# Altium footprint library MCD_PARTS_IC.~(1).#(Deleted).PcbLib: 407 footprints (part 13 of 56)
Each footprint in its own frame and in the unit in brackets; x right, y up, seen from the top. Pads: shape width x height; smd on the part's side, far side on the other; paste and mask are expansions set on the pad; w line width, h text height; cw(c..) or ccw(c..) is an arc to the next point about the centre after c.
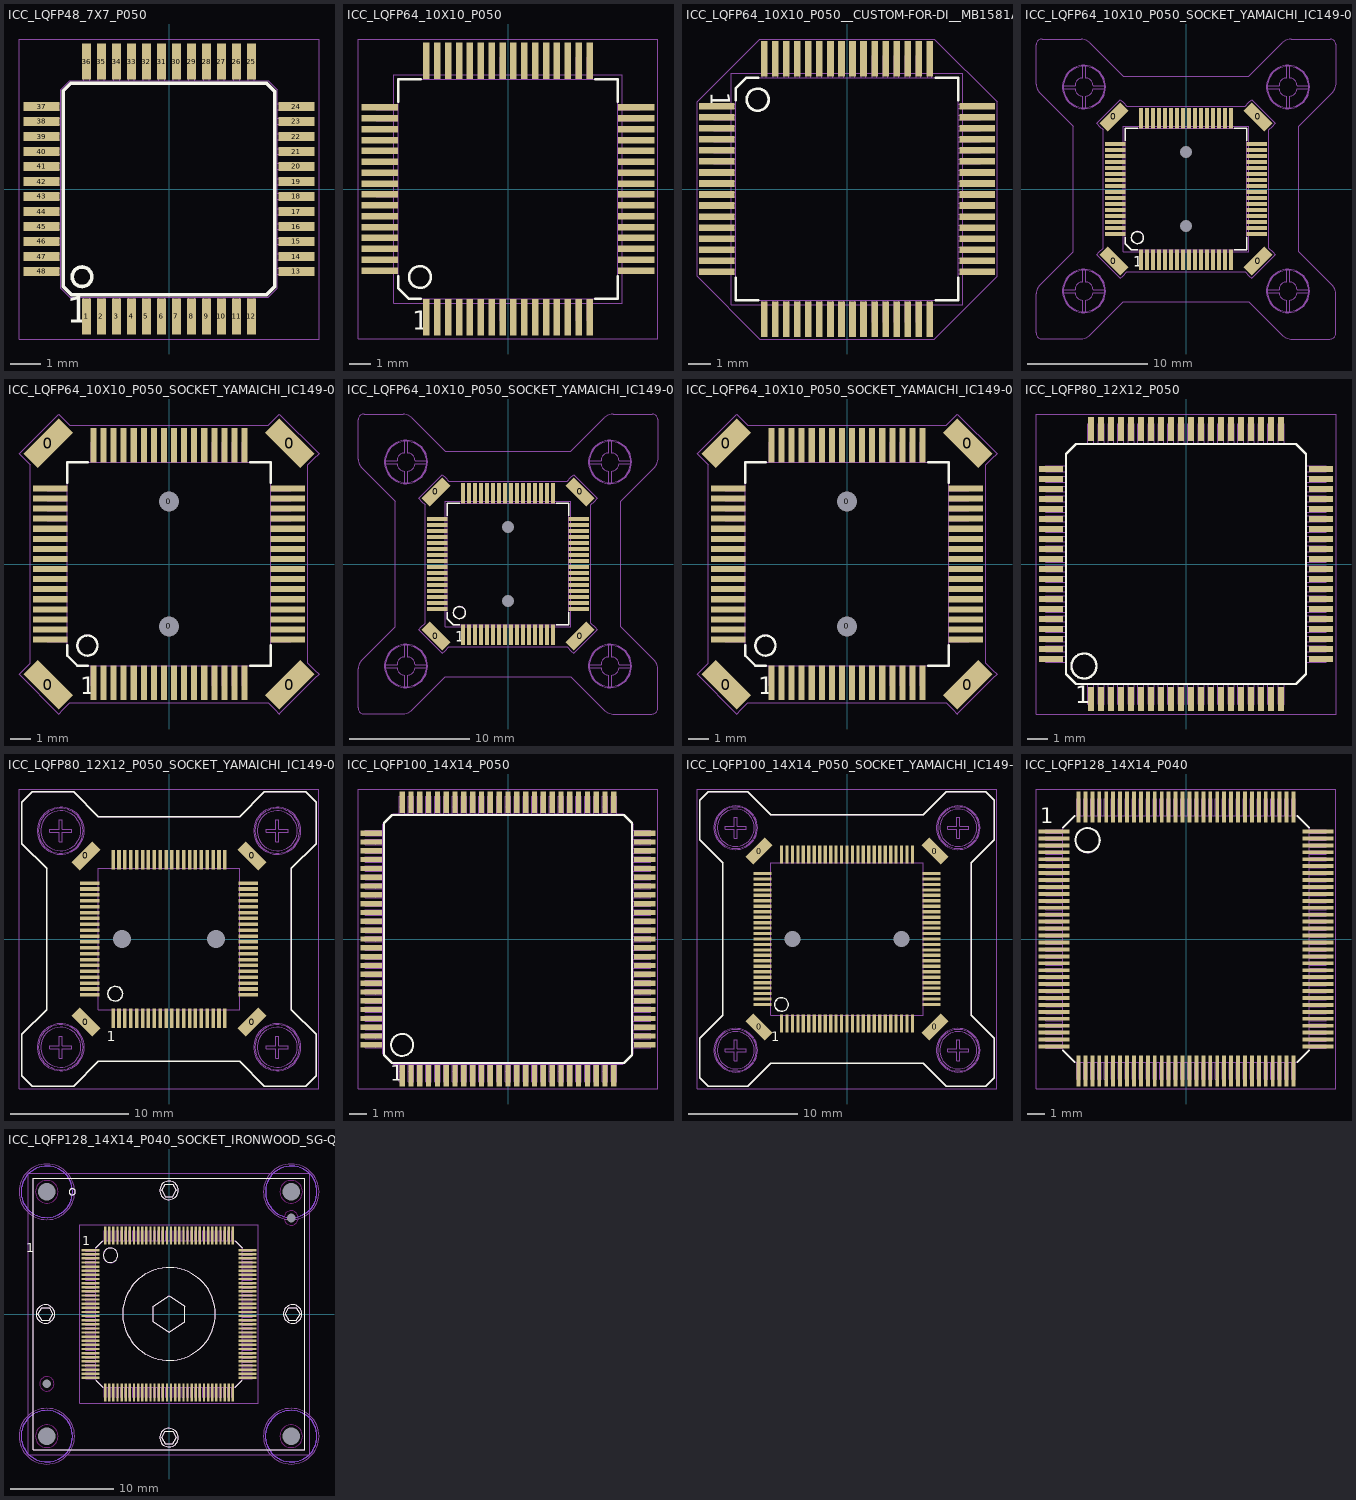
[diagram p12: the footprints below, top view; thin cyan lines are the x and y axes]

## ICC_LQFP48_7X7_P050 [mm]
height 1.6
pads (48):
  rect 0.3x1.2 smd mask+0.05: 1(-2.75,-4.25) 2(-2.25,-4.25) 3(-1.75,-4.25) 4(-1.25,-4.25) 5(-0.75,-4.25) 6(-0.25,-4.25) 7(0.25,-4.25) 8(0.75,-4.25) 9(1.25,-4.25) 10(1.75,-4.25) 11(2.25,-4.25) 12(2.75,-4.25) 25(2.75,4.25) 26(2.25,4.25) 27(1.75,4.25) 28(1.25,4.25) 29(0.75,4.25) 30(0.25,4.25) 31(-0.25,4.25) 32(-0.75,4.25) 33(-1.25,4.25) 34(-1.75,4.25) 35(-2.25,4.25) 36(-2.75,4.25)
  rect 1.2x0.3 smd mask+0.05: 13(4.25,-2.75) 14(4.25,-2.25) 15(4.25,-1.75) 16(4.25,-1.25) 17(4.25,-0.75) 18(4.25,-0.25) 19(4.25,0.25) 20(4.25,0.75) 21(4.25,1.25) 22(4.25,1.75) 23(4.25,2.25) 24(4.25,2.75) 37(-4.25,2.75) 38(-4.25,2.25) 39(-4.25,1.75) 40(-4.25,1.25) 41(-4.25,0.75) 42(-4.25,0.25) 43(-4.25,-0.25) 44(-4.25,-0.75) 45(-4.25,-1.25) 46(-4.25,-1.75) 47(-4.25,-2.25) 48(-4.25,-2.75)
Top Overlay:
  circle w0.12: c-2.9,-2.925 r0.326
  lines w0.12: -3.525,-3.25 -3.525,3 -3.525,3.275 -3.275,3.525 -2.95,3.525 2.85,3.525 3.25,3.525 3.525,3.25 3.525,-2.8 3.525,-3.25 3.25,-3.525 -2.775,-3.525 -3.25,-3.525 -3.525,-3.25
  text "1" at -3.4,-4.75 h1.5
M14-Top Assembly:
  drawing of 209 lines, arcs and shapes, not listed
  text "1" at -3.325,-4.65 h1.5
  text "'.Designator'" at -2,-0.5 h0.75
M16-Top Courtyard:
  lines w0.025: -5,-5 5,-5 5,5 -5,5 -5,-5
3D body "LQFP48_7X7_P050.STEP": height 1.6, standoff 0, extent -4.5,-4.5 4.5,4.5
3D body: height 1.6, standoff 0, extent -3.585,-3.585 3.585,3.585

## ICC_LQFP64_10X10_P050 [mm]
height 1.6
pads (64):
  rect 0.3x1.7 smd mask+0.05: 1(-3.75,-5.9) 2(-3.25,-5.9) 3(-2.75,-5.9) 4(-2.25,-5.9) 5(-1.75,-5.9) 6(-1.25,-5.9) 7(-0.75,-5.9) 8(-0.25,-5.9) 9(0.25,-5.9) 10(0.75,-5.9) 11(1.25,-5.9) 12(1.75,-5.9) 13(2.25,-5.9) 14(2.75,-5.9) 15(3.25,-5.9) 16(3.75,-5.9) 33(3.75,5.9) 34(3.25,5.9) 35(2.75,5.9) 36(2.25,5.9) 37(1.75,5.9) 38(1.25,5.9) 39(0.75,5.9) 40(0.25,5.9) 41(-0.25,5.9) 42(-0.75,5.9) 43(-1.25,5.9) 44(-1.75,5.9) 45(-2.25,5.9) 46(-2.75,5.9) 47(-3.25,5.9) 48(-3.75,5.9)
  rect 1.7x0.3 smd mask+0.05: 17(5.9,-3.75) 18(5.9,-3.25) 19(5.9,-2.75) 20(5.9,-2.25) 21(5.9,-1.75) 22(5.9,-1.25) 23(5.9,-0.75) 24(5.9,-0.25) 25(5.9,0.25) 26(5.9,0.75) 27(5.9,1.25) 28(5.9,1.75) 29(5.9,2.25) 30(5.9,2.75) 31(5.9,3.25) 32(5.9,3.75) 49(-5.9,3.75) 50(-5.9,3.25) 51(-5.9,2.75) 52(-5.9,2.25) 53(-5.9,1.75) 54(-5.9,1.25) 55(-5.9,0.75) 56(-5.9,0.25) 57(-5.9,-0.25) 58(-5.9,-0.75) 59(-5.9,-1.25) 60(-5.9,-1.75) 61(-5.9,-2.25) 62(-5.9,-2.75) 63(-5.9,-3.25) 64(-5.9,-3.75)
Top Overlay:
  circle w0.12: c-4.05,-4.05 r0.5
  lines w0.12: -5.05,-4.025 -5.05,-4.55 -4.55,-5.05 -4.025,-5.05 ; -5.05,4.025 -5.05,5.05 -4.025,5.05 ; 4.025,-5.05 5.05,-5.05 5.05,-4.025 ; 4.025,5.05 5.05,5.05 5.05,4.025
  text "1" at -4.4,-6.775 h1.5
M14-Top Assembly:
  drawing of 202 lines, arcs and shapes, not listed
  text "'.Designator'" at -2,-0.5 h0.75
  text "1" at -3.95,-6.9 h1.2
  text "16" at 3.275,-6.875 h1.2
  text "17" at 6.95,-4.275 h1.2
  text "32" at 6.9,3.2 h1.2
  text "33" at 4.3,6.925 h1.2
  text "48" at -3.15,6.9 h1.2
  text "49" at -6.925,4.325 h1.2
  text "64" at -6.925,-3.175 h1.2
M16-Top Courtyard:
  lines w0.01: -6.9,-6.9 6.9,-6.9 6.9,6.9 -4.925,6.9 -5.675,6.9 -6.9,6.9 -6.9,4.925 -6.9,-6.9
3D body: height 1.6, standoff 0, extent -5.25,-5.25 5.25,5.25
3D body "LQFP64_10X10_P050.STEP": height 1.56, standoff 0, extent -6,-6 6,6

## ICC_LQFP64_10X10_P050__CUSTOM-FOR-DI__MB1581A [mm]
height 13.2
pads (64):
  rect 1.6x0.3 smd mask+0.05: 1(-5.9,3.75) 2(-5.9,3.25) 3(-5.9,2.75) 4(-5.9,2.25) 5(-5.9,1.75) 6(-5.9,1.25) 7(-5.9,0.75) 8(-5.9,0.25) 9(-5.9,-0.25) 10(-5.9,-0.75) 11(-5.9,-1.25) 12(-5.9,-1.75) 13(-5.9,-2.25) 14(-5.9,-2.75) 15(-5.9,-3.25) 16(-5.9,-3.75) 33(5.9,-3.75) 34(5.9,-3.25) 35(5.9,-2.75) 36(5.9,-2.25) 37(5.9,-1.75) 38(5.9,-1.25) 39(5.9,-0.75) 40(5.9,-0.25) 41(5.9,0.25) 42(5.9,0.75) 43(5.9,1.25) 44(5.9,1.75) 45(5.9,2.25) 46(5.9,2.75) 47(5.9,3.25) 48(5.9,3.75)
  rect 0.3x1.6 smd mask+0.05: 17(-3.75,-5.9) 18(-3.25,-5.9) 19(-2.75,-5.9) 20(-2.25,-5.9) 21(-1.75,-5.9) 22(-1.25,-5.9) 23(-0.75,-5.9) 24(-0.25,-5.9) 25(0.25,-5.9) 26(0.75,-5.9) 27(1.25,-5.9) 28(1.75,-5.9) 29(2.25,-5.9) 30(2.75,-5.9) 31(3.25,-5.9) 32(3.75,-5.9) 49(3.75,5.9) 50(3.25,5.9) 51(2.75,5.9) 52(2.25,5.9) 53(1.75,5.9) 54(1.25,5.9) 55(0.75,5.9) 56(0.25,5.9) 57(-0.25,5.9) 58(-0.75,5.9) 59(-1.25,5.9) 60(-1.75,5.9) 61(-2.25,5.9) 62(-2.75,5.9) 63(-3.25,5.9) 64(-3.75,5.9)
Top Overlay:
  circle w0.12: c-4.05,4.05 r0.5
  lines w0.12: -5.05,-4.025 -5.05,-5.05 -4.025,-5.05 ; -5.05,4.025 -5.05,4.55 -4.55,5.05 -4.025,5.05 ; 4.025,-5.05 5.05,-5.05 5.05,-4.025 ; 4.025,5.05 5.05,5.05 5.05,4.025
  text "1" at -6.475,4.4 h1.5
M14-Top Assembly:
  drawing of 202 lines, arcs and shapes, not listed
  text "64" at -3.175,6.925 h1.2
  text "49" at 4.325,6.925 h1.2
  text "48" at 6.9,3.15 h1.2
  text "33" at 6.925,-4.3 h1.2
  text "32" at 3.2,-6.9 h1.2
  text "17" at -4.275,-6.95 h1.2
  text "16" at -6.875,-3.275 h1.2
  text "1" at -6.9,3.95 h1.2
  text "'.Designator'" at -2,-0.5 h0.75
M16-Top Courtyard:
  lines w0.01: -6.8,-3.95 -6.8,3.95 -3.95,6.8 3.95,6.8 6.8,3.95 6.8,-3.95 3.95,-6.8 -3.95,-6.8 -6.8,-3.95
3D body "LQFP64_10X10_P050.STEP": height 1.56, standoff 0, extent -6,-6 6,6

## ICC_LQFP64_10X10_P050_SOCKET_YAMAICHI_IC149-064-069-B5 [mm]
height 12.6
pads (70):
  rect 1x2.5 smd rot 45 mask+0.05: 0(-6,-6) 0(6,6)
  rect 1x2.5 smd rot 135 mask+0.05: 0(-6,6) 0(6,-6)
  round 0.5 hole 1 unplated mask+0.05: 0(0,-3.1) 0(0,3.1)
  rect 0.3x1.7 smd mask+0.05: 1(-3.75,-5.9) 2(-3.25,-5.9) 3(-2.75,-5.9) 4(-2.25,-5.9) 5(-1.75,-5.9) 6(-1.25,-5.9) 7(-0.75,-5.9) 8(-0.25,-5.9) 9(0.25,-5.9) 10(0.75,-5.9) 11(1.25,-5.9) 12(1.75,-5.9) 13(2.25,-5.9) 14(2.75,-5.9) 15(3.25,-5.9) 16(3.75,-5.9) 33(3.75,5.9) 34(3.25,5.9) 35(2.75,5.9) 36(2.25,5.9) 37(1.75,5.9) 38(1.25,5.9) 39(0.75,5.9) 40(0.25,5.9) 41(-0.25,5.9) 42(-0.75,5.9) 43(-1.25,5.9) 44(-1.75,5.9) 45(-2.25,5.9) 46(-2.75,5.9) 47(-3.25,5.9) 48(-3.75,5.9)
  rect 1.7x0.3 smd mask+0.05: 17(5.9,-3.75) 18(5.9,-3.25) 19(5.9,-2.75) 20(5.9,-2.25) 21(5.9,-1.75) 22(5.9,-1.25) 23(5.9,-0.75) 24(5.9,-0.25) 25(5.9,0.25) 26(5.9,0.75) 27(5.9,1.25) 28(5.9,1.75) 29(5.9,2.25) 30(5.9,2.75) 31(5.9,3.25) 32(5.9,3.75) 49(-5.9,3.75) 50(-5.9,3.25) 51(-5.9,2.75) 52(-5.9,2.25) 53(-5.9,1.75) 54(-5.9,1.25) 55(-5.9,0.75) 56(-5.9,0.25) 57(-5.9,-0.25) 58(-5.9,-0.75) 59(-5.9,-1.25) 60(-5.9,-1.75) 61(-5.9,-2.25) 62(-5.9,-2.75) 63(-5.9,-3.25) 64(-5.9,-3.75)
Top Overlay:
  circle w0.12: c-4.05,-4.05 r0.5
  lines w0.12: -5.05,-4.025 -5.05,-4.55 -4.55,-5.05 -4.025,-5.05 ; -5.05,4.025 -5.05,5.05 -4.025,5.05 ; 4.025,-5.05 5.05,-5.05 5.05,-4.025 ; 4.025,5.05 5.05,5.05 5.05,4.025
  text "1" at -4.4,-6.775 h1.5
M14-Top Assembly:
  drawing of 301 lines, arcs and shapes, not listed
  text "64" at -6.925,-3.175 h1.2
  text "49" at -6.925,4.325 h1.2
  text "48" at -3.15,6.9 h1.2
  text "33" at 4.3,6.925 h1.2
  text "32" at 6.9,3.2 h1.2
  text "17" at 6.95,-4.275 h1.2
  text "16" at 3.275,-6.875 h1.2
  text "1" at -3.95,-6.9 h1.2
  text "'.Designator'" at -2,-0.5 h0.75
M16-Top Courtyard:
  lines w0.01: 5.475,-7.45 5.25,-7.225 4.925,-6.9 -4.925,-6.9 -5.25,-7.225 -5.475,-7.45 -7.45,-5.475 -7.225,-5.25 -6.9,-4.925 -6.9,4.925 -7.225,5.25 -7.45,5.475 -5.7,7.225 -5.475,7.45 -5.25,7.225 -4.925,6.9 4.925,6.9 5.25,7.225 5.475,7.45 7.45,5.475 7.225,5.25 6.9,4.925 6.9,-4.925 7.225,-5.25 7.45,-5.475 7.275,-5.65 ; 5.475,-7.45 5.475,-7.45 ; 5.475,-7.45 7.275,-5.65 ; 7.275,-5.65 7.275,-5.65
3D body: height 11, standoff 3.5, extent -9.4,-9.4 -5.25,-5.25
3D body: height 11, standoff 3.5, extent -9.4,-9.4 9.4,9.4
3D body: height 3.5, standoff 0, extent -5.25,-5.25 5.25,5.25
3D body: height 0.2, standoff 0, extent 3.65,-6.675 3.85,-5.25
3D body: height 0.2, standoff 0, extent 3.15,-6.675 3.35,-5.25
3D body: height 0.2, standoff 0, extent 2.65,-6.675 2.85,-5.25
3D body: height 0.2, standoff 0, extent 2.15,-6.675 2.35,-5.25
3D body: height 0.2, standoff 0, extent 1.65,-6.675 1.85,-5.25
3D body: height 0.2, standoff 0, extent 1.15,-6.675 1.35,-5.25
3D body: height 0.2, standoff 0, extent 0.65,-6.675 0.85,-5.25
3D body: height 0.2, standoff 0, extent 0.15,-6.675 0.35,-5.25
3D body: height 0.2, standoff 0, extent -0.35,-6.675 -0.15,-5.25
3D body: height 0.2, standoff 0, extent -0.85,-6.675 -0.65,-5.25
3D body: height 0.2, standoff 0, extent -1.35,-6.675 -1.15,-5.25
3D body: height 0.2, standoff 0, extent -1.85,-6.675 -1.65,-5.25
3D body: height 0.2, standoff 0, extent -2.35,-6.675 -2.15,-5.25
3D body: height 0.2, standoff 0, extent -2.85,-6.675 -2.65,-5.25
3D body: height 0.2, standoff 0, extent -3.35,-6.675 -3.15,-5.25
3D body: height 0.2, standoff 0, extent -3.85,-6.675 -3.65,-5.25
3D body: height 0.2, standoff 0, extent -6.675,-3.85 -5.25,-3.65
3D body: height 0.2, standoff 0, extent -6.675,-3.35 -5.25,-3.15
3D body: height 0.2, standoff 0, extent -6.675,-2.85 -5.25,-2.65
3D body: height 0.2, standoff 0, extent -6.675,-2.35 -5.25,-2.15
3D body: height 0.2, standoff 0, extent -6.675,-1.85 -5.25,-1.65
3D body: height 0.2, standoff 0, extent -6.675,-1.35 -5.25,-1.15
3D body: height 0.2, standoff 0, extent -6.675,-0.85 -5.25,-0.65
3D body: height 0.2, standoff 0, extent -6.675,-0.35 -5.25,-0.15
3D body: height 0.2, standoff 0, extent -6.675,0.15 -5.25,0.35
3D body: height 0.2, standoff 0, extent -6.675,0.65 -5.25,0.85
3D body: height 0.2, standoff 0, extent -6.675,1.15 -5.25,1.35
3D body: height 0.2, standoff 0, extent -6.675,1.65 -5.25,1.85
3D body: height 0.2, standoff 0, extent -6.675,2.15 -5.25,2.35
3D body: height 0.2, standoff 0, extent -6.675,2.65 -5.25,2.85
3D body: height 0.2, standoff 0, extent -6.675,3.15 -5.25,3.35
3D body: height 0.2, standoff 0, extent -6.675,3.65 -5.25,3.85
3D body: height 0.2, standoff 0, extent 5.25,-3.85 6.675,-3.65
3D body: height 0.2, standoff 0, extent 5.25,-3.35 6.675,-3.15
3D body: height 0.2, standoff 0, extent 5.25,-2.85 6.675,-2.65
3D body: height 0.2, standoff 0, extent 5.25,-2.35 6.675,-2.15
3D body: height 0.2, standoff 0, extent 5.25,-1.85 6.675,-1.65
3D body: height 0.2, standoff 0, extent 5.25,-1.35 6.675,-1.15
3D body: height 0.2, standoff 0, extent 5.25,-0.85 6.675,-0.65
3D body: height 0.2, standoff 0, extent 5.25,-0.35 6.675,-0.15
3D body: height 0.2, standoff 0, extent 5.25,0.15 6.675,0.35
3D body: height 0.2, standoff 0, extent 5.25,0.65 6.675,0.85
3D body: height 0.2, standoff 0, extent 5.25,1.15 6.675,1.35
3D body: height 0.2, standoff 0, extent 5.25,1.65 6.675,1.85
3D body: height 0.2, standoff 0, extent 5.25,2.15 6.675,2.35
3D body: height 0.2, standoff 0, extent 5.25,2.65 6.675,2.85
3D body: height 0.2, standoff 0, extent 5.25,3.15 6.675,3.35
3D body: height 0.2, standoff 0, extent 5.25,3.65 6.675,3.85
3D body: height 0.2, standoff 0, extent 3.65,5.25 3.85,6.675
3D body: height 0.2, standoff 0, extent 3.15,5.25 3.35,6.675
3D body: height 0.2, standoff 0, extent 2.65,5.25 2.85,6.675
3D body: height 0.2, standoff 0, extent 2.15,5.25 2.35,6.675
3D body: height 0.2, standoff 0, extent 1.65,5.25 1.85,6.675
3D body: height 0.2, standoff 0, extent 1.15,5.25 1.35,6.675
3D body: height 0.2, standoff 0, extent 0.65,5.25 0.85,6.675
3D body: height 0.2, standoff 0, extent 0.15,5.25 0.35,6.675
3D body: height 0.2, standoff 0, extent -0.35,5.25 -0.15,6.675
3D body: height 0.2, standoff 0, extent -0.85,5.25 -0.65,6.675
3D body: height 0.2, standoff 0, extent -1.35,5.25 -1.15,6.675
3D body: height 0.2, standoff 0, extent -1.85,5.25 -1.65,6.675
3D body: height 0.2, standoff 0, extent -2.35,5.25 -2.15,6.675
3D body: height 0.2, standoff 0, extent -2.85,5.25 -2.65,6.675
3D body: height 0.2, standoff 0, extent -3.35,5.25 -3.15,6.675
3D body: height 11, standoff 3, extent -12.5,5.25 -5.25,12.5
3D body: height 12.6, standoff 11, extent -10.3,6.7 -6.7,10.3
3D body: height 12.6, standoff 11, extent 6.7,6.7 10.3,10.3
3D body: height 11, standoff 3, extent 5.25,5.25 12.5,12.5
3D body: height 12.6, standoff 11, extent 6.7,-10.3 10.3,-6.7
3D body: height 11, standoff 3, extent 5.25,-12.5 12.5,-5.25
3D body: height 12.6, standoff 11, extent -10.3,-10.3 -6.7,-6.7
3D body: height 11, standoff 3, extent -12.5,-12.5 -5.25,-5.25
3D body: height 3.5, standoff 0, extent -7.025,4.975 -4.975,7.025
3D body: height 3.5, standoff 0, extent 4.975,4.975 7.025,7.025
3D body: height 3.5, standoff 0, extent 4.975,-7.025 7.025,-4.975
3D body: height 3.5, standoff 0, extent -7.025,-7.025 -4.975,-4.975
3D body: height 0.2, standoff 0, extent -3.85,5.25 -3.65,6.675
3D body "LQFP64_10X10_P050.STEP": height 5.06, standoff 3.5, extent -6,-6 6,6

## ICC_LQFP64_10X10_P050_SOCKET_YAMAICHI_IC149-064-069-B5_NM [mm]
height 1.6
pads (70):
  rect 1x2.5 smd rot 45 mask+0.05: 0(-6,-6) 0(6,6)
  rect 1x2.5 smd rot 135 mask+0.05: 0(-6,6) 0(6,-6)
  round 0.5 hole 1 unplated mask+0.05: 0(0,-3.1) 0(0,3.1)
  rect 0.3x1.7 smd mask+0.05: 1(-3.75,-5.9) 2(-3.25,-5.9) 3(-2.75,-5.9) 4(-2.25,-5.9) 5(-1.75,-5.9) 6(-1.25,-5.9) 7(-0.75,-5.9) 8(-0.25,-5.9) 9(0.25,-5.9) 10(0.75,-5.9) 11(1.25,-5.9) 12(1.75,-5.9) 13(2.25,-5.9) 14(2.75,-5.9) 15(3.25,-5.9) 16(3.75,-5.9) 33(3.75,5.9) 34(3.25,5.9) 35(2.75,5.9) 36(2.25,5.9) 37(1.75,5.9) 38(1.25,5.9) 39(0.75,5.9) 40(0.25,5.9) 41(-0.25,5.9) 42(-0.75,5.9) 43(-1.25,5.9) 44(-1.75,5.9) 45(-2.25,5.9) 46(-2.75,5.9) 47(-3.25,5.9) 48(-3.75,5.9)
  rect 1.7x0.3 smd mask+0.05: 17(5.9,-3.75) 18(5.9,-3.25) 19(5.9,-2.75) 20(5.9,-2.25) 21(5.9,-1.75) 22(5.9,-1.25) 23(5.9,-0.75) 24(5.9,-0.25) 25(5.9,0.25) 26(5.9,0.75) 27(5.9,1.25) 28(5.9,1.75) 29(5.9,2.25) 30(5.9,2.75) 31(5.9,3.25) 32(5.9,3.75) 49(-5.9,3.75) 50(-5.9,3.25) 51(-5.9,2.75) 52(-5.9,2.25) 53(-5.9,1.75) 54(-5.9,1.25) 55(-5.9,0.75) 56(-5.9,0.25) 57(-5.9,-0.25) 58(-5.9,-0.75) 59(-5.9,-1.25) 60(-5.9,-1.75) 61(-5.9,-2.25) 62(-5.9,-2.75) 63(-5.9,-3.25) 64(-5.9,-3.75)
Top Overlay:
  circle w0.12: c-4.05,-4.05 r0.5
  lines w0.12: -5.05,-4.025 -5.05,-4.55 -4.55,-5.05 -4.025,-5.05 ; -5.05,4.025 -5.05,5.05 -4.025,5.05 ; 4.025,-5.05 5.05,-5.05 5.05,-4.025 ; 4.025,5.05 5.05,5.05 5.05,4.025
  text "1" at -4.4,-6.775 h1.5
M14-Top Assembly:
  drawing of 198 lines, arcs and shapes, not listed
  text "1" at -3.95,-6.9 h1.2
  text "16" at 3.275,-6.875 h1.2
  text "17" at 6.95,-4.275 h1.2
  text "32" at 6.9,3.2 h1.2
  text "33" at 4.3,6.925 h1.2
  text "48" at -3.15,6.9 h1.2
  text "49" at -6.925,4.325 h1.2
  text "64" at -6.925,-3.175 h1.2
  text "'.Designator'" at -2,-0.5 h0.75
M16-Top Courtyard:
  lines w0.01: 5.475,-7.45 7.275,-5.65 ; 5.475,-7.45 5.475,-7.45 ; 5.475,-7.45 5.25,-7.225 4.925,-6.9 -4.925,-6.9 -5.25,-7.225 -5.475,-7.45 -7.45,-5.475 -7.225,-5.25 -6.9,-4.925 -6.9,4.925 -7.225,5.25 -7.45,5.475 -5.7,7.225 -5.475,7.45 -5.25,7.225 -4.925,6.9 4.925,6.9 5.25,7.225 5.475,7.45 7.45,5.475 7.225,5.25 6.9,4.925 6.9,-4.925 7.225,-5.25 7.45,-5.475 7.275,-5.65 ; 7.275,-5.65 7.275,-5.65
3D body "LQFP64_10X10_P050.STEP": height 1.56, standoff 0, extent -6,-6 6,6
3D body: height 1.6, standoff 0, extent -5.05,-5.05 5.05,5.05

## ICC_LQFP64_10X10_P050_SOCKET_YAMAICHI_IC149-064-169-B5 [mm] "MCD-04420"
height 12.6
pads (70):
  rect 1x2.5 smd rot 45 mask+0.05: 0(-6,-6) 0(6,6)
  rect 1x2.5 smd rot 135 mask+0.05: 0(-6,6) 0(6,-6)
  round 0.5 hole 1 unplated mask+0.05: 0(0,-3.1) 0(0,3.1)
  rect 0.3x1.7 smd mask+0.05: 1(-3.75,-5.9) 2(-3.25,-5.9) 3(-2.75,-5.9) 4(-2.25,-5.9) 5(-1.75,-5.9) 6(-1.25,-5.9) 7(-0.75,-5.9) 8(-0.25,-5.9) 9(0.25,-5.9) 10(0.75,-5.9) 11(1.25,-5.9) 12(1.75,-5.9) 13(2.25,-5.9) 14(2.75,-5.9) 15(3.25,-5.9) 16(3.75,-5.9) 33(3.75,5.9) 34(3.25,5.9) 35(2.75,5.9) 36(2.25,5.9) 37(1.75,5.9) 38(1.25,5.9) 39(0.75,5.9) 40(0.25,5.9) 41(-0.25,5.9) 42(-0.75,5.9) 43(-1.25,5.9) 44(-1.75,5.9) 45(-2.25,5.9) 46(-2.75,5.9) 47(-3.25,5.9) 48(-3.75,5.9)
  rect 1.7x0.3 smd mask+0.05: 17(5.9,-3.75) 18(5.9,-3.25) 19(5.9,-2.75) 20(5.9,-2.25) 21(5.9,-1.75) 22(5.9,-1.25) 23(5.9,-0.75) 24(5.9,-0.25) 25(5.9,0.25) 26(5.9,0.75) 27(5.9,1.25) 28(5.9,1.75) 29(5.9,2.25) 30(5.9,2.75) 31(5.9,3.25) 32(5.9,3.75) 49(-5.9,3.75) 50(-5.9,3.25) 51(-5.9,2.75) 52(-5.9,2.25) 53(-5.9,1.75) 54(-5.9,1.25) 55(-5.9,0.75) 56(-5.9,0.25) 57(-5.9,-0.25) 58(-5.9,-0.75) 59(-5.9,-1.25) 60(-5.9,-1.75) 61(-5.9,-2.25) 62(-5.9,-2.75) 63(-5.9,-3.25) 64(-5.9,-3.75)
Top Overlay:
  circle w0.12: c-4.05,-4.05 r0.5
  lines w0.12: -5.05,-4.025 -5.05,-4.55 -4.55,-5.05 -4.025,-5.05 ; -5.05,4.025 -5.05,5.05 -4.025,5.05 ; 4.025,-5.05 5.05,-5.05 5.05,-4.025 ; 4.025,5.05 5.05,5.05 5.05,4.025
  text "1" at -4.4,-6.775 h1.5
M14-Top Assembly:
  drawing of 301 lines, arcs and shapes, not listed
  text "'.Designator'" at 0,0 h0.75
  text "1" at -3.95,-6.9 h1.2
  text "16" at 3.275,-6.875 h1.2
  text "17" at 6.95,-4.275 h1.2
  text "32" at 6.9,3.2 h1.2
  text "33" at 4.3,6.925 h1.2
  text "48" at -3.15,6.9 h1.2
  text "49" at -6.925,4.325 h1.2
  text "64" at -6.925,-3.175 h1.2
M16-Top Courtyard:
  lines w0.01: 5.475,-7.45 7.275,-5.65 ; 5.475,-7.45 5.475,-7.45 ; 5.475,-7.45 5.25,-7.225 4.925,-6.9 -4.925,-6.9 -5.25,-7.225 -5.475,-7.45 -7.45,-5.475 -7.225,-5.25 -6.9,-4.925 -6.9,4.925 -7.225,5.25 -7.45,5.475 -5.7,7.225 -5.475,7.45 -5.25,7.225 -4.925,6.9 4.925,6.9 5.25,7.225 5.475,7.45 7.45,5.475 7.225,5.25 6.9,4.925 6.9,-4.925 7.225,-5.25 7.45,-5.475 7.275,-5.65 ; 7.275,-5.65 7.275,-5.65
3D body "LQFP64_10X10_P050.STEP": height 5.06, standoff 3.5, extent -6,-6 6,6
3D body: height 0.2, standoff 0, extent -3.85,5.25 -3.65,6.675
3D body: height 3.5, standoff 0, extent -7.025,-7.025 -4.975,-4.975
3D body: height 3.5, standoff 0, extent 4.975,-7.025 7.025,-4.975
3D body: height 3.5, standoff 0, extent 4.975,4.975 7.025,7.025
3D body: height 3.5, standoff 0, extent -7.025,4.975 -4.975,7.025
3D body: height 11, standoff 3, extent -12.5,-12.5 -5.25,-5.25
3D body: height 12.6, standoff 11, extent -10.3,-10.3 -6.7,-6.7
3D body: height 11, standoff 3, extent 5.25,-12.5 12.5,-5.25
3D body: height 12.6, standoff 11, extent 6.7,-10.3 10.3,-6.7
3D body: height 11, standoff 3, extent 5.25,5.25 12.5,12.5
3D body: height 12.6, standoff 11, extent 6.7,6.7 10.3,10.3
3D body: height 12.6, standoff 11, extent -10.3,6.7 -6.7,10.3
3D body: height 11, standoff 3, extent -12.5,5.25 -5.25,12.5
3D body: height 0.2, standoff 0, extent -3.35,5.25 -3.15,6.675
3D body: height 0.2, standoff 0, extent -2.85,5.25 -2.65,6.675
3D body: height 0.2, standoff 0, extent -2.35,5.25 -2.15,6.675
3D body: height 0.2, standoff 0, extent -1.85,5.25 -1.65,6.675
3D body: height 0.2, standoff 0, extent -1.35,5.25 -1.15,6.675
3D body: height 0.2, standoff 0, extent -0.85,5.25 -0.65,6.675
3D body: height 0.2, standoff 0, extent -0.35,5.25 -0.15,6.675
3D body: height 0.2, standoff 0, extent 0.15,5.25 0.35,6.675
3D body: height 0.2, standoff 0, extent 0.65,5.25 0.85,6.675
3D body: height 0.2, standoff 0, extent 1.15,5.25 1.35,6.675
3D body: height 0.2, standoff 0, extent 1.65,5.25 1.85,6.675
3D body: height 0.2, standoff 0, extent 2.15,5.25 2.35,6.675
3D body: height 0.2, standoff 0, extent 2.65,5.25 2.85,6.675
3D body: height 0.2, standoff 0, extent 3.15,5.25 3.35,6.675
3D body: height 0.2, standoff 0, extent 3.65,5.25 3.85,6.675
3D body: height 0.2, standoff 0, extent 5.25,3.65 6.675,3.85
3D body: height 0.2, standoff 0, extent 5.25,3.15 6.675,3.35
3D body: height 0.2, standoff 0, extent 5.25,2.65 6.675,2.85
3D body: height 0.2, standoff 0, extent 5.25,2.15 6.675,2.35
3D body: height 0.2, standoff 0, extent 5.25,1.65 6.675,1.85
3D body: height 0.2, standoff 0, extent 5.25,1.15 6.675,1.35
3D body: height 0.2, standoff 0, extent 5.25,0.65 6.675,0.85
3D body: height 0.2, standoff 0, extent 5.25,0.15 6.675,0.35
3D body: height 0.2, standoff 0, extent 5.25,-0.35 6.675,-0.15
3D body: height 0.2, standoff 0, extent 5.25,-0.85 6.675,-0.65
3D body: height 0.2, standoff 0, extent 5.25,-1.35 6.675,-1.15
3D body: height 0.2, standoff 0, extent 5.25,-1.85 6.675,-1.65
3D body: height 0.2, standoff 0, extent 5.25,-2.35 6.675,-2.15
3D body: height 0.2, standoff 0, extent 5.25,-2.85 6.675,-2.65
3D body: height 0.2, standoff 0, extent 5.25,-3.35 6.675,-3.15
3D body: height 0.2, standoff 0, extent 5.25,-3.85 6.675,-3.65
3D body: height 0.2, standoff 0, extent -6.675,3.65 -5.25,3.85
3D body: height 0.2, standoff 0, extent -6.675,3.15 -5.25,3.35
3D body: height 0.2, standoff 0, extent -6.675,2.65 -5.25,2.85
3D body: height 0.2, standoff 0, extent -6.675,2.15 -5.25,2.35
3D body: height 0.2, standoff 0, extent -6.675,1.65 -5.25,1.85
3D body: height 0.2, standoff 0, extent -6.675,1.15 -5.25,1.35
3D body: height 0.2, standoff 0, extent -6.675,0.65 -5.25,0.85
3D body: height 0.2, standoff 0, extent -6.675,0.15 -5.25,0.35
3D body: height 0.2, standoff 0, extent -6.675,-0.35 -5.25,-0.15
3D body: height 0.2, standoff 0, extent -6.675,-0.85 -5.25,-0.65
3D body: height 0.2, standoff 0, extent -6.675,-1.35 -5.25,-1.15
3D body: height 0.2, standoff 0, extent -6.675,-1.85 -5.25,-1.65
3D body: height 0.2, standoff 0, extent -6.675,-2.35 -5.25,-2.15
3D body: height 0.2, standoff 0, extent -6.675,-2.85 -5.25,-2.65
3D body: height 0.2, standoff 0, extent -6.675,-3.35 -5.25,-3.15
3D body: height 0.2, standoff 0, extent -6.675,-3.85 -5.25,-3.65
3D body: height 0.2, standoff 0, extent -3.85,-6.675 -3.65,-5.25
3D body: height 0.2, standoff 0, extent -3.35,-6.675 -3.15,-5.25
3D body: height 0.2, standoff 0, extent -2.85,-6.675 -2.65,-5.25
3D body: height 0.2, standoff 0, extent -2.35,-6.675 -2.15,-5.25
3D body: height 0.2, standoff 0, extent -1.85,-6.675 -1.65,-5.25
3D body: height 0.2, standoff 0, extent -1.35,-6.675 -1.15,-5.25
3D body: height 0.2, standoff 0, extent -0.85,-6.675 -0.65,-5.25
3D body: height 0.2, standoff 0, extent -0.35,-6.675 -0.15,-5.25
3D body: height 0.2, standoff 0, extent 0.15,-6.675 0.35,-5.25
3D body: height 0.2, standoff 0, extent 0.65,-6.675 0.85,-5.25
3D body: height 0.2, standoff 0, extent 1.15,-6.675 1.35,-5.25
3D body: height 0.2, standoff 0, extent 1.65,-6.675 1.85,-5.25
3D body: height 0.2, standoff 0, extent 2.15,-6.675 2.35,-5.25
3D body: height 0.2, standoff 0, extent 2.65,-6.675 2.85,-5.25
3D body: height 0.2, standoff 0, extent 3.15,-6.675 3.35,-5.25
3D body: height 0.2, standoff 0, extent 3.65,-6.675 3.85,-5.25
3D body: height 3.5, standoff 0, extent -5.25,-5.25 5.25,5.25
3D body: height 11, standoff 3.5, extent -9.4,-9.4 9.4,9.4
3D body: height 11, standoff 3.5, extent -9.4,-9.4 -5.25,-5.25

## ICC_LQFP64_10X10_P050_SOCKET_YAMAICHI_IC149-064-169-B5_NM [mm] "MCD-04420"
height 1.6
pads (70):
  rect 1x2.5 smd rot 45 mask+0.05: 0(-6,-6) 0(6,6)
  rect 1x2.5 smd rot 135 mask+0.05: 0(-6,6) 0(6,-6)
  round 0.5 hole 1 unplated mask+0.05: 0(0,-3.1) 0(0,3.1)
  rect 0.3x1.7 smd mask+0.05: 1(-3.75,-5.9) 2(-3.25,-5.9) 3(-2.75,-5.9) 4(-2.25,-5.9) 5(-1.75,-5.9) 6(-1.25,-5.9) 7(-0.75,-5.9) 8(-0.25,-5.9) 9(0.25,-5.9) 10(0.75,-5.9) 11(1.25,-5.9) 12(1.75,-5.9) 13(2.25,-5.9) 14(2.75,-5.9) 15(3.25,-5.9) 16(3.75,-5.9) 33(3.75,5.9) 34(3.25,5.9) 35(2.75,5.9) 36(2.25,5.9) 37(1.75,5.9) 38(1.25,5.9) 39(0.75,5.9) 40(0.25,5.9) 41(-0.25,5.9) 42(-0.75,5.9) 43(-1.25,5.9) 44(-1.75,5.9) 45(-2.25,5.9) 46(-2.75,5.9) 47(-3.25,5.9) 48(-3.75,5.9)
  rect 1.7x0.3 smd mask+0.05: 17(5.9,-3.75) 18(5.9,-3.25) 19(5.9,-2.75) 20(5.9,-2.25) 21(5.9,-1.75) 22(5.9,-1.25) 23(5.9,-0.75) 24(5.9,-0.25) 25(5.9,0.25) 26(5.9,0.75) 27(5.9,1.25) 28(5.9,1.75) 29(5.9,2.25) 30(5.9,2.75) 31(5.9,3.25) 32(5.9,3.75) 49(-5.9,3.75) 50(-5.9,3.25) 51(-5.9,2.75) 52(-5.9,2.25) 53(-5.9,1.75) 54(-5.9,1.25) 55(-5.9,0.75) 56(-5.9,0.25) 57(-5.9,-0.25) 58(-5.9,-0.75) 59(-5.9,-1.25) 60(-5.9,-1.75) 61(-5.9,-2.25) 62(-5.9,-2.75) 63(-5.9,-3.25) 64(-5.9,-3.75)
Top Overlay:
  circle w0.12: c-4.05,-4.05 r0.5
  lines w0.12: -5.05,-4.025 -5.05,-4.55 -4.55,-5.05 -4.025,-5.05 ; -5.05,4.025 -5.05,5.05 -4.025,5.05 ; 4.025,-5.05 5.05,-5.05 5.05,-4.025 ; 4.025,5.05 5.05,5.05 5.05,4.025
  text "1" at -4.4,-6.775 h1.5
M14-Top Assembly:
  drawing of 198 lines, arcs and shapes, not listed
  text "'.Designator'" at 0,0 h0.75
  text "64" at -6.925,-3.175 h1.2
  text "49" at -6.925,4.325 h1.2
  text "48" at -3.15,6.9 h1.2
  text "33" at 4.3,6.925 h1.2
  text "32" at 6.9,3.2 h1.2
  text "17" at 6.95,-4.275 h1.2
  text "16" at 3.275,-6.875 h1.2
  text "1" at -3.95,-6.9 h1.2
M16-Top Courtyard:
  lines w0.01: 5.475,-7.45 5.25,-7.225 4.925,-6.9 -4.925,-6.9 -5.25,-7.225 -5.475,-7.45 -7.45,-5.475 -7.225,-5.25 -6.9,-4.925 -6.9,4.925 -7.225,5.25 -7.45,5.475 -5.7,7.225 -5.475,7.45 -5.25,7.225 -4.925,6.9 4.925,6.9 5.25,7.225 5.475,7.45 7.45,5.475 7.225,5.25 6.9,4.925 6.9,-4.925 7.225,-5.25 7.45,-5.475 7.275,-5.65 ; 5.475,-7.45 5.475,-7.45 ; 5.475,-7.45 7.275,-5.65 ; 7.275,-5.65 7.275,-5.65
3D body: height 1.6, standoff 0, extent -5.05,-5.05 5.05,5.05
3D body "LQFP64_10X10_P050.STEP": height 1.56, standoff 0, extent -6,-6 6,6

## ICC_LQFP80_12X12_P050 [mm] "MCD-02690"
height 1.6
pads (80):
  rect 0.3x1.2 smd mask+0.05: 1(-4.75,-6.75) 2(-4.25,-6.75) 3(-3.75,-6.75) 4(-3.25,-6.75) 5(-2.75,-6.75) 6(-2.25,-6.75) 7(-1.75,-6.75) 8(-1.25,-6.75) 9(-0.75,-6.75) 10(-0.25,-6.75) 11(0.25,-6.75) 12(0.75,-6.75) 13(1.25,-6.75) 14(1.75,-6.75) 15(2.25,-6.75) 16(2.75,-6.75) 17(3.25,-6.75) 18(3.75,-6.75) 19(4.25,-6.75) 20(4.75,-6.75) 41(4.75,6.75) 42(4.25,6.75) 43(3.75,6.75) 44(3.25,6.75) 45(2.75,6.75) 46(2.25,6.75) 47(1.75,6.75) 48(1.25,6.75) 49(0.75,6.75) 50(0.25,6.75) 51(-0.25,6.75) 52(-0.75,6.75) 53(-1.25,6.75) 54(-1.75,6.75) 55(-2.25,6.75) 56(-2.75,6.75) 57(-3.25,6.75) 58(-3.75,6.75) 59(-4.25,6.75) 60(-4.75,6.75)
  rect 1.2x0.3 smd mask+0.05: 21(6.75,-4.75) 22(6.75,-4.25) 23(6.75,-3.75) 24(6.75,-3.25) 25(6.75,-2.75) 26(6.75,-2.25) 27(6.75,-1.75) 28(6.75,-1.25) 29(6.75,-0.75) 30(6.75,-0.25) 31(6.75,0.25) 32(6.75,0.75) 33(6.75,1.25) 34(6.75,1.75) 35(6.75,2.25) 36(6.75,2.75) 37(6.75,3.25) 38(6.75,3.75) 39(6.75,4.25) 40(6.75,4.75) 61(-6.75,4.75) 62(-6.75,4.25) 63(-6.75,3.75) 64(-6.75,3.25) 65(-6.75,2.75) 66(-6.75,2.25) 67(-6.75,1.75) 68(-6.75,1.25) 69(-6.75,0.75) 70(-6.75,0.25) 71(-6.75,-0.25) 72(-6.75,-0.75) 73(-6.75,-1.25) 74(-6.75,-1.75) 75(-6.75,-2.25) 76(-6.75,-2.75) 77(-6.75,-3.25) 78(-6.75,-3.75) 79(-6.75,-4.25) 80(-6.75,-4.75)
Top Overlay:
  circle w0.12: c-5.1,-5.1 r0.625
  lines w0.12: -6,-5.5 -5.5,-6 5.5,-6 6,-5.5 6,5.5 5.5,6 -5.5,6 -6,5.5 -6,-5.5
  text "1" at -5.55,-7.25 h1.5
Top Assembly:
  drawing of 329 lines, arcs and shapes, not listed
  text "41" at 5.2,6.975 h1
  text "60" at -4.35,7 h1
  text "21" at 6.975,-5.2 h1
  text "40" at 7,4.35 h1
  text "'.Designator'" at -2,-0.5 h0.75
  text "80" at -7,-4.35 h1
  text "61" at -6.975,5.2 h1
  text "20" at 4.35,-7 h1
  text "1" at -4.9,-6.975 h1
Top Courtyard:
  lines w0.01: -7.5,-7.5 7.5,-7.5 7.5,7.5 -7.5,7.5 -7.5,-7.5
3D body "User Library-LQFP-80.STEP": height 1.43, standoff -0.01, extent -6.9,-6.9 6.9,6.9

## ICC_LQFP80_12X12_P050_SOCKET_YAMAICHI_IC149-080-130-B5 [mm] "MCD-03131"
height 13.2
pads (86):
  rect 1x2.5 smd rot 45 mask+0.05: 0(-7.071,-7.071) 0(7.071,7.071)
  rect 1x2.5 smd rot 135 mask+0.05: 0(-7.071,7.071) 0(7.071,-7.071)
  round 0 hole 1.5 unplated mask+0.05: 0(-4,0) 0(4,0)
  rect 0.3x1.65 smd mask+0.05: 1(-4.75,-6.725) 2(-4.25,-6.725) 3(-3.75,-6.725) 4(-3.25,-6.725) 5(-2.75,-6.725) 6(-2.25,-6.725) 7(-1.75,-6.725) 8(-1.25,-6.725) 9(-0.75,-6.725) 10(-0.25,-6.725) 11(0.25,-6.725) 12(0.75,-6.725) 13(1.25,-6.725) 14(1.75,-6.725) 15(2.25,-6.725) 16(2.75,-6.725) 17(3.25,-6.725) 18(3.75,-6.725) 19(4.25,-6.725) 20(4.75,-6.725) 41(4.75,6.725) 42(4.25,6.725) 43(3.75,6.725) 44(3.25,6.725) 45(2.75,6.725) 46(2.25,6.725) 47(1.75,6.725) 48(1.25,6.725) 49(0.75,6.725) 50(0.25,6.725) 51(-0.25,6.725) 52(-0.75,6.725) 53(-1.25,6.725) 54(-1.75,6.725) 55(-2.25,6.725) 56(-2.75,6.725) 57(-3.25,6.725) 58(-3.75,6.725) 59(-4.25,6.725) 60(-4.75,6.725)
  rect 1.65x0.3 smd mask+0.05: 21(6.725,-4.75) 22(6.725,-4.25) 23(6.725,-3.75) 24(6.725,-3.25) 25(6.725,-2.75) 26(6.725,-2.25) 27(6.725,-1.75) 28(6.725,-1.25) 29(6.725,-0.75) 30(6.725,-0.25) 31(6.725,0.25) 32(6.725,0.75) 33(6.725,1.25) 34(6.725,1.75) 35(6.725,2.25) 36(6.725,2.75) 37(6.725,3.25) 38(6.725,3.75) 39(6.725,4.25) 40(6.725,4.75) 61(-6.75,4.75) 62(-6.75,4.25) 63(-6.75,3.75) 64(-6.75,3.25) 65(-6.75,2.75) 66(-6.75,2.25) 67(-6.75,1.75) 68(-6.75,1.25) 69(-6.75,0.75) 70(-6.75,0.25) 71(-6.75,-0.25) 72(-6.75,-0.75) 73(-6.75,-1.25) 74(-6.75,-1.75) 75(-6.75,-2.25) 76(-6.75,-2.75) 77(-6.75,-3.25) 78(-6.75,-3.75) 79(-6.75,-4.25) 80(-6.75,-4.75)
Top Overlay:
  circle w0.12: c-4.575,-4.65 r0.625
  lines w0.12: -12.5,-11.625 -11.625,-12.5 -8.1,-12.5 -6,-10.4 6,-10.4 8.1,-12.5 11.625,-12.5 12.5,-11.625 12.5,-8.1 10.4,-6 10.4,6 12.5,8.1 12.5,11.625 11.625,12.5 8.1,12.5 6,10.4 -6,10.4 -8.1,12.5 -11.625,12.5 -12.5,11.625 -12.5,8.1 -10.4,6 -10.4,-6 -12.5,-8.1 -12.5,-11.625
  text "1" at -5.3,-9 h1.5
M14-Top Assembly:
  circle w0.01: c-9.2,9.2 r2
  circle w0.01: c-9.2,9.2 r1.901
  circle w0.01: c-9.2,9.2 r1.7
  circle w0.01: c-9.2,-9.2 r2
  circle w0.01: c-9.2,-9.2 r1.901
  circle w0.01: c-9.2,-9.2 r1.7
  circle w0.01: c9.2,-9.2 r2
  circle w0.01: c9.2,-9.2 r1.901
  circle w0.01: c9.2,-9.2 r1.7
  circle w0.01: c9.2,9.2 r2
  circle w0.01: c9.2,9.2 r1.901
  circle w0.01: c9.2,9.2 r1.7
  lines w0.01: -12.5,-11.625 -11.625,-12.5 -8.1,-12.5 -6,-10.4 6,-10.4 8.1,-12.5 11.625,-12.5 12.5,-11.625 12.5,-8.1 10.4,-6 10.4,6 12.5,8.1 12.5,11.625 11.625,12.5 8.1,12.5 6,10.4 -6,10.4 -8.1,12.5 -11.625,12.5 -12.5,11.625 -12.5,8.1 -10.4,6 -10.4,-6 -12.5,-8.1 -12.5,-11.625 ; -10.15,-9.325 -10.15,-9.2 -10.15,-9.075 -9.325,-9.075 -9.325,-8.25 -9.2,-8.25 -9.075,-8.25 -9.075,-9.075 -8.25,-9.075 -8.25,-9.2 -8.25,-9.325 -9.075,-9.325 -9.075,-10.15 -9.2,-10.15 -9.325,-10.15 -9.325,-9.325 -10.15,-9.325 ; -10.15,9.075 -9.325,9.075 -9.325,8.25 -9.2,8.25 -9.075,8.25 -9.075,9.075 -8.25,9.075 -8.25,9.2 -8.25,9.325 -9.075,9.325 -9.075,10.15 -9.2,10.15 -9.325,10.15 -9.325,9.325 -10.15,9.325 -10.15,9.2 -10.15,9.075 ; -6,-6 6,-6 6,6 -6,6 -6,-6 ; 8.25,-9.325 9.075,-9.325 9.075,-10.15 9.2,-10.15 9.325,-10.15 9.325,-9.325 10.15,-9.325 10.15,-9.2 10.15,-9.075 9.325,-9.075 9.325,-8.25 9.2,-8.25 9.075,-8.25 9.075,-9.075 8.25,-9.075 8.25,-9.2 8.25,-9.325 ; 8.25,9.075 9.075,9.075 9.075,8.25 9.2,8.25 9.325,8.25 9.325,9.075 10.15,9.075 10.15,9.2 10.15,9.325 9.325,9.325 9.325,10.15 9.2,10.15 9.075,10.15 9.075,9.325 8.25,9.325 8.25,9.2 8.25,9.075
  text "20" at 4.6,-6.725 h1
  text "'.Designator'" at -2,-0.5 h0.75
  text "1" at -4.9,-6.725 h1
  text "21" at 6.933,-4.9 h1
  text "40" at 6.725,4.6 h1
  text "41" at 5.15,6.975 h1
  text "60" at -4.525,6.975 h1
  text "61" at -7.1,5.425 h1
  text "80" at -6.75,-4.6 h1
M16-Top Courtyard:
  lines w0.01: -12.75,-12.75 -12.75,12.75 12.75,12.75 12.75,-12.75 -12.75,-12.75
3D body "User Library-LQFP-80.STEP": height 1.43, standoff -0.01, extent -6.9,-6.9 6.9,6.9
3D body: height 11, standoff 3.5, extent -12.5,-12.5 12.5,0
3D body: height 11, standoff 3.5, extent -12.5,0 12.5,12.5
3D body: height 13.2, standoff 11, extent -11.2,-11.2 -7.2,-7.2
3D body: height 13.2, standoff 11, extent 7.2,-11.2 11.2,-7.2
3D body: height 13.2, standoff 11, extent 7.2,7.2 11.2,11.2
3D body: height 13.2, standoff 11, extent -11.2,7.2 -7.2,11.2
3D body: height 3.5, standoff 0, extent -8.29,5.852 -5.852,8.29
3D body: height 3.5, standoff 0, extent 5.852,5.852 8.29,8.29
3D body: height 3.5, standoff 0, extent 5.852,-8.29 8.29,-5.852
3D body: height 3.5, standoff 0, extent -8.29,-8.29 -5.852,-5.852

## ICC_LQFP100_14X14_P050 [mm] "MCD-01438"
height 1.6
pads (100):
  rect 0.3x1.2 smd mask+0.05: 1(-6,-7.75) 2(-5.5,-7.75) 3(-5,-7.75) 4(-4.5,-7.75) 5(-4,-7.75) 6(-3.5,-7.75) 7(-3,-7.75) 8(-2.5,-7.75) 9(-2,-7.75) 10(-1.5,-7.75) 11(-1,-7.75) 12(-0.5,-7.75) 13(0,-7.75) 14(0.5,-7.75) 15(1,-7.75) 16(1.5,-7.75) 17(2,-7.75) 18(2.5,-7.75) 19(3,-7.75) 20(3.5,-7.75) 21(4,-7.75) 22(4.5,-7.75) 23(5,-7.75) 24(5.5,-7.75) 25(6,-7.75) 51(6,7.75) 52(5.5,7.75) 53(5,7.75) 54(4.5,7.75) 55(4,7.75) 56(3.5,7.75) 57(3,7.75) 58(2.5,7.75) 59(2,7.75) 60(1.5,7.75) 61(1,7.75) 62(0.5,7.75) 63(0,7.75) 64(-0.5,7.75) 65(-1,7.75) 66(-1.5,7.75) 67(-2,7.75) 68(-2.5,7.75) 69(-3,7.75) 70(-3.5,7.75) 71(-4,7.75) 72(-4.5,7.75) 73(-5,7.75) 74(-5.5,7.75) 75(-6,7.75)
  rect 1.2x0.3 smd mask+0.05: 26(7.75,-6) 27(7.75,-5.5) 28(7.75,-5) 29(7.75,-4.5) 30(7.75,-4) 31(7.75,-3.5) 32(7.75,-3) 33(7.75,-2.5) 34(7.75,-2) 35(7.75,-1.5) 36(7.75,-1) 37(7.75,-0.5) 38(7.75,0) 39(7.75,0.5) 40(7.75,1) 41(7.75,1.5) 42(7.75,2) 43(7.75,2.5) 44(7.75,3) 45(7.75,3.5) 46(7.75,4) 47(7.75,4.5) 48(7.75,5) 49(7.75,5.5) 50(7.75,6) 76(-7.75,6) 77(-7.75,5.5) 78(-7.75,5) 79(-7.75,4.5) 80(-7.75,4) 81(-7.75,3.5) 82(-7.75,3) 83(-7.75,2.5) 84(-7.75,2) 85(-7.75,1.5) 86(-7.75,1) 87(-7.75,0.5) 88(-7.75,0) 89(-7.75,-0.5) 90(-7.75,-1) 91(-7.75,-1.5) 92(-7.75,-2) 93(-7.75,-2.5) 94(-7.75,-3) 95(-7.75,-3.5) 96(-7.75,-4) 97(-7.75,-4.5) 98(-7.75,-5) 99(-7.75,-5.5) 100(-7.75,-6)
Top Overlay:
  circle w0.12: c-6,-6 r0.625
  lines w0.12: -7.025,-6.575 -7.025,6.2 -7.025,6.575 -6.575,7.025 6.575,7.025 7.025,6.575 7.025,-6.575 6.575,-7.025 -6.575,-7.025 -7.025,-6.575
  text "1" at -6.675,-8.35 h1.5
M14-Top Assembly:
  drawing of 409 lines, arcs and shapes, not listed
  text "25" at 5.55,-8.075 h1
  text "'.Designator'" at -2,-0.5 h0.75
  text "1" at -6.125,-8.075 h1
  text "26" at 8.075,-6.45 h1
  text "50" at 8.075,5.55 h1
  text "51" at 6.4,8.075 h1
  text "75" at -5.525,8.075 h1
  text "76" at -8.075,6.45 h1
  text "100" at -8.075,-5.325 h1
M16-Top Courtyard:
  lines w0.01: -8.5,-8.5 8.5,-8.5 8.5,8.5 -8.5,8.5 -8.5,6.1 -8.5,-8.5
3D body: height 1.6, standoff 0, extent -7.1,-7.1 7.1,7.1
3D body: height 1.61, standoff 1.6, extent -6.595,-6.599 -5.4,-5.401
3D body "LQFP100_05.STEP": height 1.6, standoff 0, extent -8,-8 8,8

## ICC_LQFP100_14X14_P050_SOCKET_YAMAICHI_IC149-100-125-B5 [mm] "MCD-03131"
height 13.2
pads (106):
  rect 1x2.5 smd rot 45 mask+0.05: 0(-8.061,-8.061) 0(8.061,8.061)
  rect 1x2.5 smd rot 135 mask+0.05: 0(-8.061,8.061) 0(8.061,-8.061)
  round 0 hole 1.5 unplated mask+0.05: 0(-5,0) 0(5,0)
  rect 0.3x1.65 smd mask+0.05: 1(-6,-7.725) 2(-5.5,-7.725) 3(-5,-7.725) 4(-4.5,-7.725) 5(-4,-7.725) 6(-3.5,-7.725) 7(-3,-7.725) 8(-2.5,-7.725) 9(-2,-7.725) 10(-1.5,-7.725) 11(-1,-7.725) 12(-0.5,-7.725) 13(0,-7.725) 14(0.5,-7.725) 15(1,-7.725) 16(1.5,-7.725) 17(2,-7.725) 18(2.5,-7.725) 19(3,-7.725) 20(3.5,-7.725) 21(4,-7.725) 22(4.5,-7.725) 23(5,-7.725) 24(5.5,-7.725) 25(6,-7.725) 51(6,7.725) 52(5.5,7.725) 53(5,7.725) 54(4.5,7.725) 55(4,7.725) 56(3.5,7.725) 57(3,7.725) 58(2.5,7.725) 59(2,7.725) 60(1.5,7.725) 61(1,7.725) 62(0.5,7.725) 63(0,7.725) 64(-0.5,7.725) 65(-1,7.725) 66(-1.5,7.725) 67(-2,7.725) 68(-2.5,7.725) 69(-3,7.725) 70(-3.5,7.725) 71(-4,7.725) 72(-4.5,7.725) 73(-5,7.725) 74(-5.5,7.725) 75(-6,7.725)
  rect 1.65x0.3 smd mask+0.05: 26(7.725,-6) 27(7.725,-5.5) 28(7.725,-5) 29(7.725,-4.5) 30(7.725,-4) 31(7.725,-3.5) 32(7.725,-3) 33(7.725,-2.5) 34(7.725,-2) 35(7.725,-1.5) 36(7.725,-1) 37(7.725,-0.5) 38(7.725,0) 39(7.725,0.5) 40(7.725,1) 41(7.725,1.5) 42(7.725,2) 43(7.725,2.5) 44(7.725,3) 45(7.725,3.5) 46(7.725,4) 47(7.725,4.5) 48(7.725,5) 49(7.725,5.5) 50(7.725,6) 76(-7.725,6) 77(-7.725,5.5) 78(-7.725,5) 79(-7.725,4.5) 80(-7.725,4) 81(-7.725,3.5) 82(-7.725,3) 83(-7.725,2.5) 84(-7.725,2) 85(-7.725,1.5) 86(-7.725,1) 87(-7.725,0.5) 88(-7.725,0) 89(-7.725,-0.5) 90(-7.725,-1) 91(-7.725,-1.5) 92(-7.725,-2) 93(-7.725,-2.5) 94(-7.725,-3) 95(-7.725,-3.5) 96(-7.725,-4) 97(-7.725,-4.5) 98(-7.725,-5) 99(-7.725,-5.5) 100(-7.725,-6)
Top Overlay:
  circle w0.12: c-6,-6 r0.625
  lines w0.12: -9.1,-13.5 -12.714,-13.5 -13.5,-12.714 -13.5,-9.1 -11.4,-7 -11.4,7 -13.5,9.1 -13.5,12.714 -12.714,13.5 -9.1,13.5 -7,11.4 7,11.4 9.1,13.5 ; -9.1,-13.5 -7,-11.4 7,-11.4 9.1,-13.5 ; 9.1,-13.5 12.714,-13.5 13.5,-12.714 13.5,-9.1 ; 9.1,13.5 12.714,13.5 13.5,12.714 13.5,9.1 11.4,7 11.4,-7 13.5,-9.1
  text "1" at -6.925,-9.7 h1.5
M14-Top Assembly:
  circle w0.01: c10.2,10.2 r1.7
  circle w0.01: c10.2,10.2 r1.901
  circle w0.01: c10.2,10.2 r2
  circle w0.01: c10.2,-10.2 r1.7
  circle w0.01: c10.2,-10.2 r1.901
  circle w0.01: c10.2,-10.2 r2
  circle w0.01: c-10.2,-10.2 r1.7
  circle w0.01: c-10.2,-10.2 r1.901
  circle w0.01: c-10.2,-10.2 r2
  circle w0.01: c-10.2,10.2 r1.7
  circle w0.01: c-10.2,10.2 r1.901
  circle w0.01: c-10.2,10.2 r2
  lines w0.01: -9.1,-13.5 -12.714,-13.5 -13.5,-12.714 -13.5,-9.1 -11.4,-7 -11.4,7 -13.5,9.1 -13.5,12.714 -12.714,13.5 -9.1,13.5 -7,11.4 7,11.4 9.1,13.5 ; -9.1,-13.5 -7,-11.4 7,-11.4 9.1,-13.5 ; 9.1,-13.5 12.714,-13.5 13.5,-12.714 13.5,-9.1 ; 9.1,13.5 12.714,13.5 13.5,12.714 13.5,9.1 11.4,7 11.4,-7 13.5,-9.1 ; -11.15,-10.325 -10.325,-10.325 -10.325,-11.15 -10.2,-11.15 -10.075,-11.15 -10.075,-10.325 -9.25,-10.325 -9.25,-10.2 -9.25,-10.075 -10.075,-10.075 -10.075,-9.25 -10.2,-9.25 -10.325,-9.25 -10.325,-10.075 -11.15,-10.075 -11.15,-10.2 -11.15,-10.325 ; -11.15,10.075 -11.15,10.2 -11.15,10.325 -10.325,10.325 -10.325,11.15 -10.2,11.15 -10.075,11.15 -10.075,10.325 -9.25,10.325 -9.25,10.2 -9.25,10.075 -10.075,10.075 -10.075,9.25 -10.2,9.25 -10.325,9.25 -10.325,10.075 -11.15,10.075 ; -7,-7 -7,7 7,7 7,-7 -7,-7 ; 9.25,-10.325 9.25,-10.2 9.25,-10.075 10.075,-10.075 10.075,-9.25 10.2,-9.25 10.325,-9.25 10.325,-10.075 11.15,-10.075 11.15,-10.2 11.15,-10.325 10.325,-10.325 10.325,-11.15 10.2,-11.15 10.075,-11.15 10.075,-10.325 9.25,-10.325 ; 9.25,10.075 9.25,10.2 9.25,10.325 10.075,10.325 10.075,11.15 10.2,11.15 10.325,11.15 10.325,10.325 11.15,10.325 11.15,10.2 11.15,10.075 10.325,10.075 10.325,9.25 10.2,9.25 10.075,9.25 10.075,10.075 9.25,10.075
  text "100" at -8.075,-5.325 h1
  text "76" at -8.075,6.45 h1
  text "75" at -5.525,8.075 h1
  text "51" at 6.4,8.075 h1
  text "50" at 8.075,5.55 h1
  text "26" at 8.075,-6.45 h1
  text "1" at -6.125,-8.075 h1
  text "'.Designator'" at -2,-0.5 h0.75
  text "25" at 5.55,-8.075 h1
M16-Top Courtyard:
  lines w0.01: -13.75,-13.75 -13.75,-8.5 -13.75,13.75 13.75,13.75 13.75,-13.75 -13.75,-13.75
3D body: height 3.5, standoff 0, extent -9.219,-9.219 -6.781,-6.781
3D body: height 3.5, standoff 0, extent 6.842,-9.28 9.28,-6.842
3D body: height 3.5, standoff 0, extent 6.842,6.842 9.28,9.28
3D body: height 3.5, standoff 0, extent -9.28,6.842 -6.842,9.28
3D body "LQFP100_05.STEP": height 1.6, standoff 0, extent -8,-8 8,8
3D body: height 13.2, standoff 11, extent -12.2,8.2 -8.2,12.2
3D body: height 13.2, standoff 11, extent 8.2,8.2 12.2,12.2
3D body: height 13.2, standoff 11, extent 8.2,-12.2 12.2,-8.2
3D body: height 13.2, standoff 11, extent -12.2,-12.2 -8.2,-8.2
3D body: height 11, standoff 3.5, extent -13.5,0 13.5,13.5
3D body: height 11, standoff 3.5, extent -13.5,-13.5 13.5,0

## ICC_LQFP128_14X14_P040 [mm]
height 1.6
pads (128):
  rect 1.78x0.225 smd mask+0.038: 1(-7.62,6.2) 2(-7.62,5.8) 3(-7.62,5.4) 4(-7.62,5) 5(-7.62,4.6) 6(-7.62,4.2) 7(-7.62,3.8) 8(-7.62,3.4) 9(-7.62,3) 10(-7.62,2.6) 11(-7.62,2.2) 12(-7.62,1.8) 13(-7.62,1.4) 14(-7.62,1) 15(-7.62,0.6) 16(-7.62,0.2) 17(-7.62,-0.2) 18(-7.62,-0.6) 19(-7.62,-1) 20(-7.62,-1.4) 21(-7.62,-1.8) 22(-7.62,-2.2) 23(-7.62,-2.6) 24(-7.62,-3) 25(-7.62,-3.4) 26(-7.62,-3.8) 27(-7.62,-4.2) 28(-7.62,-4.6) 29(-7.62,-5) 30(-7.62,-5.4) 31(-7.62,-5.8) 32(-7.62,-6.2) 65(7.62,-6.2) 66(7.62,-5.8) 67(7.62,-5.4) 68(7.62,-5) 69(7.62,-4.6) 70(7.62,-4.2) 71(7.62,-3.8) 72(7.62,-3.4) 73(7.62,-3) 74(7.62,-2.6) 75(7.62,-2.2) 76(7.62,-1.8) 77(7.62,-1.4) 78(7.62,-1) 79(7.62,-0.6) 80(7.62,-0.2) 81(7.62,0.2) 82(7.62,0.6) 83(7.62,1) 84(7.62,1.4) 85(7.62,1.8) 86(7.62,2.2) 87(7.62,2.6) 88(7.62,3) 89(7.62,3.4) 90(7.62,3.8) 91(7.62,4.2) 92(7.62,4.6) 93(7.62,5) 94(7.62,5.4) 95(7.62,5.8) 96(7.62,6.2)
  rect 0.225x1.78 smd mask+0.038: 33(-6.2,-7.62) 34(-5.8,-7.62) 35(-5.4,-7.62) 36(-5,-7.62) 37(-4.6,-7.62) 38(-4.2,-7.62) 39(-3.8,-7.62) 40(-3.4,-7.62) 41(-3,-7.62) 42(-2.6,-7.62) 43(-2.2,-7.62) 44(-1.8,-7.62) 45(-1.4,-7.62) 46(-1,-7.62) 47(-0.6,-7.62) 48(-0.2,-7.62) 49(0.2,-7.62) 50(0.6,-7.62) 51(1,-7.62) 52(1.4,-7.62) 53(1.8,-7.62) 54(2.2,-7.62) 55(2.6,-7.62) 56(3,-7.62) 57(3.4,-7.62) 58(3.8,-7.62) 59(4.2,-7.62) 60(4.6,-7.62) 61(5,-7.62) 62(5.4,-7.62) 63(5.8,-7.62) 64(6.2,-7.62) 97(6.2,7.62) 98(5.8,7.62) 99(5.4,7.62) 100(5,7.62) 101(4.6,7.62) 102(4.2,7.62) 103(3.8,7.62) 104(3.4,7.62) 105(3,7.62) 106(2.6,7.62) 107(2.2,7.62) 108(1.8,7.62) 109(1.4,7.62) 110(1,7.62) 111(0.6,7.62) 112(0.2,7.62) 113(-0.2,7.62) 114(-0.6,7.62) 115(-1,7.62) 116(-1.4,7.62) 117(-1.8,7.62) 118(-2.2,7.62) 119(-2.6,7.62) 120(-3,7.62) 121(-3.4,7.62) 122(-3.8,7.62) 123(-4.2,7.62) 124(-4.6,7.62) 125(-5,7.62) 126(-5.4,7.62) 127(-5.8,7.62) 128(-6.2,7.62)
Top Overlay:
  circle w0.12: c-5.675,5.7 r0.7
  lines w0.12: -7.1,-6.425 -6.425,-7.1 ; -7.1,6.425 -6.425,7.1 ; 6.425,-7.1 7.1,-6.425 ; 6.425,7.1 7.1,6.425
  text "1" at -8.4,6.375 h1.5
M14-Top Assembly:
  drawing of 393 lines, arcs and shapes, not listed
  text "'.Designator'" at -2,-0.5 h0.75
  text "1" at -7.5,5.875 h1
  text "128" at -6.875,7.275 h1
  text "32" at -8.15,-6.525 h1
  text "33" at -6.675,-7.9 h1
  text "64" at 5.75,-7.9 h1
  text "65" at 7.25,-6.525 h1
  text "96" at 7.25,5.875 h1
  text "97" at 5.75,7.25 h1
M16-Top Courtyard:
  lines w0.01: -8.65,-8.65 8.65,-8.65 8.65,8.65 -8.65,8.65 -8.65,6.075 -8.65,-8.65
3D body "LQFP128_14X14_P040.STEP": height 1.35, standoff 0, extent -8,-8 8,8
3D body: height 1.6, standoff 0, extent -7.1,-7.1 7.1,7.1
3D body: height 1.61, standoff 1.6, extent -6.176,5.181 -5.18,6.179

## ICC_LQFP128_14X14_P040_SOCKET_IRONWOOD_SG-QFE-7011MF [mm]
height 9.85
pads (134):
  rect 1.78x0.225 smd mask+0.038: 1(-7.62,6.2) 2(-7.62,5.8) 3(-7.62,5.4) 4(-7.62,5) 5(-7.62,4.6) 6(-7.62,4.2) 7(-7.62,3.8) 8(-7.62,3.4) 9(-7.62,3) 10(-7.62,2.6) 11(-7.62,2.2) 12(-7.62,1.8) 13(-7.62,1.4) 14(-7.62,1) 15(-7.62,0.6) 16(-7.62,0.2) 17(-7.62,-0.2) 18(-7.62,-0.6) 19(-7.62,-1) 20(-7.62,-1.4) 21(-7.62,-1.8) 22(-7.62,-2.2) 23(-7.62,-2.6) 24(-7.62,-3) 25(-7.62,-3.4) 26(-7.62,-3.8) 27(-7.62,-4.2) 28(-7.62,-4.6) 29(-7.62,-5) 30(-7.62,-5.4) 31(-7.62,-5.8) 32(-7.62,-6.2) 65(7.62,-6.2) 66(7.62,-5.8) 67(7.62,-5.4) 68(7.62,-5) 69(7.62,-4.6) 70(7.62,-4.2) 71(7.62,-3.8) 72(7.62,-3.4) 73(7.62,-3) 74(7.62,-2.6) 75(7.62,-2.2) 76(7.62,-1.8) 77(7.62,-1.4) 78(7.62,-1) 79(7.62,-0.6) 80(7.62,-0.2) 81(7.62,0.2) 82(7.62,0.6) 83(7.62,1) 84(7.62,1.4) 85(7.62,1.8) 86(7.62,2.2) 87(7.62,2.6) 88(7.62,3) 89(7.62,3.4) 90(7.62,3.8) 91(7.62,4.2) 92(7.62,4.6) 93(7.62,5) 94(7.62,5.4) 95(7.62,5.8) 96(7.62,6.2)
  rect 0.225x1.78 smd mask+0.038: 33(-6.2,-7.62) 34(-5.8,-7.62) 35(-5.4,-7.62) 36(-5,-7.62) 37(-4.6,-7.62) 38(-4.2,-7.62) 39(-3.8,-7.62) 40(-3.4,-7.62) 41(-3,-7.62) 42(-2.6,-7.62) 43(-2.2,-7.62) 44(-1.8,-7.62) 45(-1.4,-7.62) 46(-1,-7.62) 47(-0.6,-7.62) 48(-0.2,-7.62) 49(0.2,-7.62) 50(0.6,-7.62) 51(1,-7.62) 52(1.4,-7.62) 53(1.8,-7.62) 54(2.2,-7.62) 55(2.6,-7.62) 56(3,-7.62) 57(3.4,-7.62) 58(3.8,-7.62) 59(4.2,-7.62) 60(4.6,-7.62) 61(5,-7.62) 62(5.4,-7.62) 63(5.8,-7.62) 64(6.2,-7.62) 97(6.2,7.62) 98(5.8,7.62) 99(5.4,7.62) 100(5,7.62) 101(4.6,7.62) 102(4.2,7.62) 103(3.8,7.62) 104(3.4,7.62) 105(3,7.62) 106(2.6,7.62) 107(2.2,7.62) 108(1.8,7.62) 109(1.4,7.62) 110(1,7.62) 111(0.6,7.62) 112(0.2,7.62) 113(-0.2,7.62) 114(-0.6,7.62) 115(-1,7.62) 116(-1.4,7.62) 117(-1.8,7.62) 118(-2.2,7.62) 119(-2.6,7.62) 120(-3,7.62) 121(-3.4,7.62) 122(-3.8,7.62) 123(-4.2,7.62) 124(-4.6,7.62) 125(-5,7.62) 126(-5.4,7.62) 127(-5.8,7.62) 128(-6.2,7.62)
  round 0 hole 1.71 unplated mask+0.05: NPTH1(-11.86,11.86) NPTH2(11.86,11.86) NPTH3(11.86,-11.86) NPTH4(-11.86,-11.86)
  round 0 hole 0.85 unplated mask+0.05: NPTH5(-11.86,-6.78) NPTH6(11.86,9.32)
Bottom Layer keep-out:
  circle w0.01: c-11.86,11.86 r2.5
  circle w0.01: c11.865,11.86 r2.5
  circle w0.01: c11.86,-11.86 r2.5
  circle w0.01: c-11.86,-11.86 r2.5
Top Overlay:
  circle w0.12: c0,0 r4.5
  circle w0.12: c-12,0 r0.9
  circle w0.12: c0,-12 r0.9
  circle w0.12: c12,0 r0.9
  circle w0.12: c0,12 r0.9
  circle w0.12: c-9.385,11.86 r0.3
  circle w0.12: c-5.675,5.7 r0.7
  lines w0.12: -7.1,-6.425 -6.425,-7.1 ; -7.1,6.425 -6.425,7.1 ; 6.425,-7.1 7.1,-6.425 ; 6.425,7.1 7.1,6.425 ; -13.175,-13.175 13.175,-13.175 13.175,13.175 -13.175,13.175 -13.175,-13.175 ; -12.72,0 -12.36,0.6 -11.64,0.6 -11.28,0 -11.64,-0.6 -12.36,-0.6 -12.72,0 ; -1.524,-0.762 0,-1.778 1.524,-0.762 1.524,0.762 0,1.778 -1.524,0.762 -1.524,-0.762 ; -0.72,-12 -0.36,-11.4 0.36,-11.4 0.72,-12 0.36,-12.6 -0.36,-12.6 -0.72,-12 ; -0.72,12 -0.36,11.4 0.36,11.4 0.72,12 0.36,12.6 -0.36,12.6 -0.72,12 ; 11.28,0 11.64,0.6 12.36,0.6 12.72,0 12.36,-0.6 11.64,-0.6 11.28,0
  text "1" at -8.4,6.375 h1.5
  text "1" at -13.843,5.715 h1.5
Bottom Overlay:
  circle w0.12: c-11.86,11.86 r2.5
  circle w0.12: c-11.86,-11.86 r2.5
  circle w0.12: c11.86,-11.86 r2.5
  circle w0.12: c11.86,11.86 r2.5
Keep-Out Layer:
  circle w0.01: c11.86,9.32 r0.7
  circle w0.01: c-11.86,11.86 r1.1
  circle w0.01: c11.86,11.86 r1.1
  circle w0.01: c11.86,-11.86 r1.1
  circle w0.01: c-11.86,-11.86 r1.1
  circle w0.01: c-11.86,-6.78 r0.7
M14-Top Assembly:
  drawing of 434 lines, arcs and shapes, not listed
  text "'.Designator'" at -2,2.5 h0.75
  text "1" at -7.5,5.875 h1
  text "128" at -6.875,7.275 h1
  text "32" at -8.15,-6.525 h1
  text "33" at -6.675,-7.9 h1
  text "64" at 5.75,-7.9 h1
  text "65" at 7.25,-6.525 h1
  text "96" at 7.25,5.875 h1
  text "97" at 5.75,7.25 h1
M15-Bottom Assembly:
  circle w0.01: c-11.86,11.86 r2.5
  circle w0.01: c-11.86,-11.86 r2.5
  circle w0.01: c11.86,-11.86 r2.5
  circle w0.01: c11.865,11.86 r2.5
M16-Top Courtyard:
  lines w0.01: -13.675,-13.675 -13.675,13.675 13.675,13.675 13.675,-13.675 -13.675,-13.675 ; -8.65,-8.65 8.65,-8.65 8.65,8.65 -8.65,8.65 -8.65,6.075 -8.65,-8.65
M17-Bottom Courtyard:
  circle w0.01: c-11.86,11.86 r2.7
  circle w0.01: c11.86,11.86 r2.7
  circle w0.01: c11.86,-11.86 r2.7
  circle w0.01: c-11.86,-11.86 r2.7
3D body: height 6.01, standoff 6, extent 11.28,-0.6 12.72,0.6
3D body: height 6.01, standoff 6, extent -0.72,-12.6 0.72,-11.4
3D body: height 6.01, standoff 6, extent -12.72,-0.6 -11.28,0.6
3D body: height 6.01, standoff 6, extent -0.72,11.4 0.72,12.6
3D body "LQFP128_14X14_P040.STEP": height 1.35, standoff 0, extent -8,-8 8,8
3D body: height 9.85, standoff 1.6, extent -4.5,-4.5 4.5,4.5
3D body: height 9.86, standoff 9.85, extent -1.524,-1.778 1.524,1.778
3D body: height 5, standoff 0, extent -13.175,-13.175 13.175,13.175
3D body: height 6, standoff 5, extent -0.893,11.102 0.9,12.898
3D body: height 6, standoff 5, extent 11.107,-0.898 12.9,0.898
3D body: height 6, standoff 5, extent -0.893,-12.898 0.9,-11.102
3D body: height 6, standoff 5, extent -12.893,-0.898 -11.1,0.898
3D body: height 0.65, standoff 0, extent -14.36,9.363 -9.36,14.357
3D body: height 0.65, standoff 0, extent 9.36,9.363 14.36,14.357
3D body: height 0.65, standoff 0, extent 9.36,-14.357 14.36,-9.363
3D body: height 0.65, standoff 0, extent -14.36,-14.357 -9.36,-9.363
3D body: height 1.45, standoff 0.65, extent -14.232,9.488 -9.488,14.232
3D body: height 1.45, standoff 0.65, extent 9.488,9.488 14.232,14.232
3D body: height 1.45, standoff 0.65, extent 9.488,-14.232 14.232,-9.488
3D body: height 1.45, standoff 0.65, extent -14.232,-14.232 -9.488,-9.488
